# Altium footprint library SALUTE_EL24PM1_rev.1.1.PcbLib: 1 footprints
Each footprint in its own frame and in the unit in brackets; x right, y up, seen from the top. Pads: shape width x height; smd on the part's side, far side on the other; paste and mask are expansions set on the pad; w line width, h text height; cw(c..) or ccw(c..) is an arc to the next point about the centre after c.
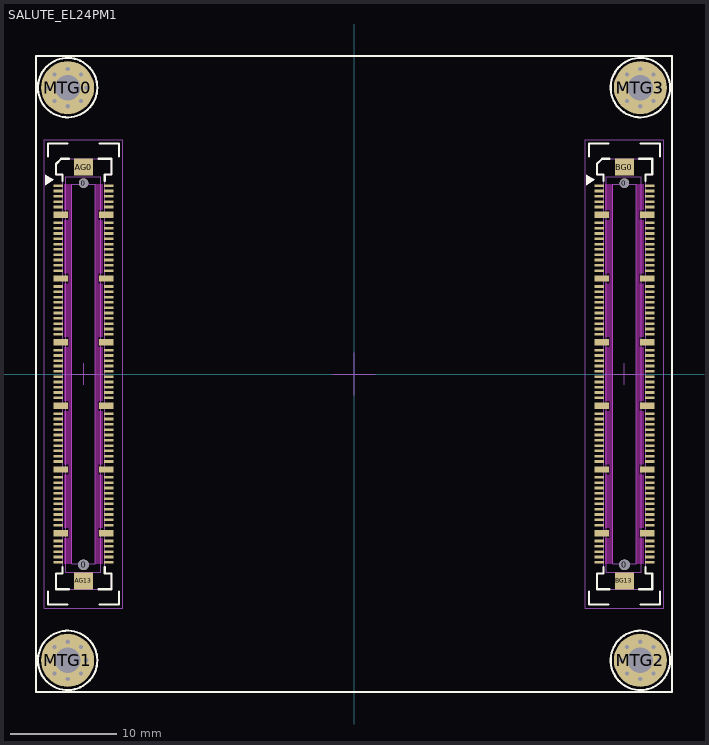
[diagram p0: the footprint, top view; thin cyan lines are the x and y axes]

## SALUTE_EL24PM1 [mm]
height 6
pads (276):
  round 1 hole 1 unplated mask+0.075: 0(-25.5,-18) 0(25.5,-18)
  round 0.9 hole 0.9 unplated mask+0.075: 0(-25.5,18) 0(25.5,18)
  rect 0.9x0.25 smd mask+0.075: A1(-27.875,17.75) A2(-23.125,17.75) A3(-27.875,17.25) A4(-23.125,17.25) A5(-27.875,16.75) A6(-23.125,16.75) A7(-27.875,16.25) A8(-23.125,16.25) A9(-27.875,15.75) A10(-23.125,15.75) A11(-27.875,14.25) A12(-23.125,14.25) A13(-27.875,13.75) A14(-23.125,13.75) A15(-27.875,13.25) A16(-23.125,13.25) A17(-27.875,12.75) A18(-23.125,12.75) A19(-27.875,12.25) A20(-23.125,12.25) A21(-27.875,11.75) A22(-23.125,11.75) A23(-27.875,11.25) A24(-23.125,11.25) A25(-27.875,10.75) A26(-23.125,10.75) A27(-27.875,10.25) A28(-23.125,10.25) A29(-27.875,9.75) A30(-23.125,9.75) A31(-27.875,8.25) A32(-23.125,8.25) A33(-27.875,7.75) A34(-23.125,7.75) A35(-27.875,7.25) A36(-23.125,7.25) A37(-27.875,6.75) A38(-23.125,6.75) A39(-27.875,6.25) A40(-23.125,6.25) A41(-27.875,5.75) A42(-23.125,5.75) A43(-27.875,5.25) A44(-23.125,5.25) A45(-27.875,4.75) A46(-23.125,4.75) A47(-27.875,4.25) A48(-23.125,4.25) A49(-27.875,3.75) A50(-23.125,3.75) A51(-27.875,2.25) A52(-23.125,2.25) A53(-27.875,1.75) A54(-23.125,1.75) A55(-27.875,1.25) A56(-23.125,1.25) A57(-27.875,0.75) A58(-23.125,0.75) A59(-27.875,0.25) A60(-23.125,0.25) A61(-27.875,-0.25) A62(-23.125,-0.25) A63(-27.875,-0.75) A64(-23.125,-0.75) A65(-27.875,-1.25) A66(-23.125,-1.25) A67(-27.875,-1.75) A68(-23.125,-1.75) A69(-27.875,-2.25) A70(-23.125,-2.25) A71(-27.875,-3.75) A72(-23.125,-3.75) A73(-27.875,-4.25) A74(-23.125,-4.25) A75(-27.875,-4.75) A76(-23.125,-4.75) A77(-27.875,-5.25) A78(-23.125,-5.25) A79(-27.875,-5.75) A80(-23.125,-5.75) A81(-27.875,-6.25) A82(-23.125,-6.25) A83(-27.875,-6.75) A84(-23.125,-6.75) A85(-27.875,-7.25) A86(-23.125,-7.25) A87(-27.875,-7.75) A88(-23.125,-7.75) A89(-27.875,-8.25) A90(-23.125,-8.25) A91(-27.875,-9.75) A92(-23.125,-9.75) A93(-27.875,-10.25) A94(-23.125,-10.25) A95(-27.875,-10.75) A96(-23.125,-10.75) A97(-27.875,-11.25) A98(-23.125,-11.25) A99(-27.875,-11.75) A100(-23.125,-11.75) A101(-27.875,-12.25) A102(-23.125,-12.25) A103(-27.875,-12.75) A104(-23.125,-12.75) A105(-27.875,-13.25) A106(-23.125,-13.25) A107(-27.875,-13.75) A108(-23.125,-13.75) A109(-27.875,-14.25) A110(-23.125,-14.25) A111(-27.875,-15.75) A112(-23.125,-15.75) A113(-27.875,-16.25) A114(-23.125,-16.25) A115(-27.875,-16.75) A116(-23.125,-16.75) A117(-27.875,-17.25) A118(-23.125,-17.25) A119(-27.875,-17.75) A120(-23.125,-17.75) B1(23.125,17.75) B2(27.875,17.75) B3(23.125,17.25) B4(27.875,17.25) B5(23.125,16.75) B6(27.875,16.75) B7(23.125,16.25) B8(27.875,16.25) B9(23.125,15.75) B10(27.875,15.75) B11(23.125,14.25) B12(27.875,14.25) B13(23.125,13.75) B14(27.875,13.75) B15(23.125,13.25) B16(27.875,13.25) B17(23.125,12.75) B18(27.875,12.75) B19(23.125,12.25) B20(27.875,12.25) B21(23.125,11.75) B22(27.875,11.75) B23(23.125,11.25) B24(27.875,11.25) B25(23.125,10.75) B26(27.875,10.75) B27(23.125,10.25) B28(27.875,10.25) B29(23.125,9.75) B30(27.875,9.75) B31(23.125,8.25) B32(27.875,8.25) B33(23.125,7.75) B34(27.875,7.75) B35(23.125,7.25) B36(27.875,7.25) B37(23.125,6.75) B38(27.875,6.75) B39(23.125,6.25) B40(27.875,6.25) B41(23.125,5.75) B42(27.875,5.75) B43(23.125,5.25) B44(27.875,5.25) B45(23.125,4.75) B46(27.875,4.75) B47(23.125,4.25) B48(27.875,4.25) B49(23.125,3.75) B50(27.875,3.75) B51(23.125,2.25) B52(27.875,2.25) B53(23.125,1.75) B54(27.875,1.75) B55(23.125,1.25) B56(27.875,1.25) B57(23.125,0.75) B58(27.875,0.75) B59(23.125,0.25) B60(27.875,0.25) B61(23.125,-0.25) B62(27.875,-0.25) B63(23.125,-0.75) B64(27.875,-0.75) B65(23.125,-1.25) B66(27.875,-1.25) B67(23.125,-1.75) B68(27.875,-1.75) B69(23.125,-2.25) B70(27.875,-2.25) B71(23.125,-3.75) B72(27.875,-3.75) B73(23.125,-4.25) B74(27.875,-4.25) B75(23.125,-4.75) B76(27.875,-4.75) B77(23.125,-5.25) B78(27.875,-5.25) B79(23.125,-5.75) B80(27.875,-5.75) B81(23.125,-6.25) B82(27.875,-6.25) B83(23.125,-6.75) B84(27.875,-6.75) B85(23.125,-7.25) B86(27.875,-7.25) B87(23.125,-7.75) B88(27.875,-7.75) B89(23.125,-8.25) B90(27.875,-8.25) B91(23.125,-9.75) B92(27.875,-9.75) B93(23.125,-10.25) B94(27.875,-10.25) B95(23.125,-10.75) B96(27.875,-10.75) B97(23.125,-11.25) B98(27.875,-11.25) B99(23.125,-11.75) B100(27.875,-11.75) B101(23.125,-12.25) B102(27.875,-12.25) B103(23.125,-12.75) B104(27.875,-12.75) B105(23.125,-13.25) B106(27.875,-13.25) B107(23.125,-13.75) B108(27.875,-13.75) B109(23.125,-14.25) B110(27.875,-14.25) B111(23.125,-15.75) B112(27.875,-15.75) B113(23.125,-16.25) B114(27.875,-16.25) B115(23.125,-16.75) B116(27.875,-16.75) B117(23.125,-17.25) B118(27.875,-17.25) B119(23.125,-17.75) B120(27.875,-17.75)
  rect 1.8x1.6 smd mask+0.075: AG0(-25.5,19.5) AG13(-25.5,-19.5) BG0(25.5,19.5) BG13(25.5,-19.5)
  rect 1.35x0.6 smd mask+0.075: AG1(-27.65,15) AG2(-23.35,15) AG3(-27.65,9) AG4(-23.35,9) AG5(-27.65,3) AG6(-23.35,3) AG7(-27.65,-3) AG8(-23.35,-3) AG9(-27.65,-9) AG10(-23.35,-9) AG11(-27.65,-15) AG12(-23.35,-15) BG1(23.35,15) BG2(27.65,15) BG3(23.35,9) BG4(27.65,9) BG5(23.35,3) BG6(27.65,3) BG7(23.35,-3) BG8(27.65,-3) BG9(23.35,-9) BG10(27.65,-9) BG11(23.35,-15) BG12(27.65,-15)
  round 5 / inner round 3.6 / far side round 5 hole 2.4: MTG0(-27,27) MTG1(-27,-27) MTG2(27,-27) MTG3(27,27)
via 25.75,28.25 diameter 1 hole 0.4
via 27,28.75 diameter 1 hole 0.4
via 28.25,28.25 diameter 1 hole 0.4
via 28.75,27 diameter 1 hole 0.4
via 28.25,25.75 diameter 1 hole 0.4
via 27,25.25 diameter 1 hole 0.4
via 25.75,25.75 diameter 1 hole 0.4
via 25.2,27 diameter 1 hole 0.4
via 25.75,-25.75 diameter 1 hole 0.4
via 27,-25.25 diameter 1 hole 0.4
via 28.25,-25.75 diameter 1 hole 0.4
via 28.75,-27 diameter 1 hole 0.4
via 28.25,-28.25 diameter 1 hole 0.4
via 27,-28.75 diameter 1 hole 0.4
via 25.75,-28.25 diameter 1 hole 0.4
via 25.2,-27 diameter 1 hole 0.4
via -28.25,-25.75 diameter 1 hole 0.4
via -27,-25.25 diameter 1 hole 0.4
via -25.75,-25.75 diameter 1 hole 0.4
via -25.25,-27 diameter 1 hole 0.4
via -25.75,-28.25 diameter 1 hole 0.4
via -27,-28.75 diameter 1 hole 0.4
via -28.25,-28.25 diameter 1 hole 0.4
via -28.8,-27 diameter 1 hole 0.4
via -28.8,27 diameter 1 hole 0.4
via -28.25,25.75 diameter 1 hole 0.4
via -27,25.25 diameter 1 hole 0.4
via -25.75,25.75 diameter 1 hole 0.4
via -25.25,27 diameter 1 hole 0.4
via -25.75,28.25 diameter 1 hole 0.4
via -27,28.75 diameter 1 hole 0.4
via -28.25,28.25 diameter 1 hole 0.4
Top Layer keep-out:
  region: 23.7,14.5 24.1,14.5 24.1,15.5 23.7,15.5 23.7,17.9 24.4,17.9 24.4,-17.9 23.7,-17.9 23.7,-15.5 24.1,-15.5 24.1,-14.5 23.7,-14.5 23.7,-9.5 24.1,-9.5 24.1,-8.5 23.7,-8.5 23.7,-3.5 24.1,-3.5 24.1,-2.5 23.7,-2.5 23.7,2.5 24.1,2.5 24.1,3.5 23.7,3.5 23.7,8.5 24.1,8.5 24.1,9.5 23.7,9.5
  region: 27.3,14.5 26.9,14.5 26.9,15.5 27.3,15.5 27.3,17.9 26.6,17.9 26.6,-17.9 27.3,-17.9 27.3,-15.5 26.9,-15.5 26.9,-14.5 27.3,-14.5 27.3,-9.5 26.9,-9.5 26.9,-8.5 27.3,-8.5 27.3,-3.5 26.9,-3.5 26.9,-2.5 27.3,-2.5 27.3,2.5 26.9,2.5 26.9,3.5 27.3,3.5 27.3,8.5 26.9,8.5 26.9,9.5 27.3,9.5
  region: -23.7,14.5 -24.1,14.5 -24.1,15.5 -23.7,15.5 -23.7,17.9 -24.4,17.9 -24.4,-17.9 -23.7,-17.9 -23.7,-15.5 -24.1,-15.5 -24.1,-14.5 -23.7,-14.5 -23.7,-9.5 -24.1,-9.5 -24.1,-8.5 -23.7,-8.5 -23.7,-3.5 -24.1,-3.5 -24.1,-2.5 -23.7,-2.5 -23.7,2.5 -24.1,2.5 -24.1,3.5 -23.7,3.5 -23.7,8.5 -24.1,8.5 -24.1,9.5 -23.7,9.5
  region: -27.3,14.5 -26.9,14.5 -26.9,15.5 -27.3,15.5 -27.3,17.9 -26.6,17.9 -26.6,-17.9 -27.3,-17.9 -27.3,-15.5 -26.9,-15.5 -26.9,-14.5 -27.3,-14.5 -27.3,-9.5 -26.9,-9.5 -26.9,-8.5 -27.3,-8.5 -27.3,-3.5 -26.9,-3.5 -26.9,-2.5 -27.3,-2.5 -27.3,2.5 -26.9,2.5 -26.9,3.5 -27.3,3.5 -27.3,8.5 -26.9,8.5 -26.9,9.5 -27.3,9.5
Top Overlay:
  circle w0.2: c27,27 r2.8
  circle w0.2: c27,-27 r2.8
  circle w0.2: c-27,-27 r2.8
  circle w0.2: c-27,27 r2.8
  region: 21.9,17.8 21.9,18.8 22.7,18.3
  region: -29.1,17.8 -29.1,18.8 -28.3,18.3
  lines w0.1: -22.875,-20.3 -22.875,-20.3 ; -22.875,20.3 -22.875,20.3 ; 28.125,-20.3 28.125,-20.3 ; 28.125,20.3 28.125,20.3
  lines w0.2: -28.85,-20.5 -28.85,-21.75 -27,-21.75 ; -28.85,20.5 -28.85,21.75 -27,21.75 ; -27.475,-18.2 -27.475,-18.8 -28.1,-18.8 -28.1,-20.3 -26.9,-20.3 ; -27.475,18.2 -27.475,18.8 -28.1,18.8 -28.1,19.8 -27.6,20.3 -26.9,20.3 ; -24.1,-20.3 -22.875,-20.3 -22.875,-18.8 -23.5,-18.8 -23.5,-18.2 ; -24.1,20.3 -22.875,20.3 -22.875,18.8 -23.5,18.8 -23.5,18.2 ; -24,-21.75 -22.15,-21.75 -22.15,-20.5 ; -24,21.75 -22.15,21.75 -22.15,20.5 ; 22.15,-20.5 22.15,-21.75 24,-21.75 ; 22.15,20.5 22.15,21.75 24,21.75 ; 23.525,-18.2 23.525,-18.8 22.9,-18.8 22.9,-20.3 24.1,-20.3 ; 23.525,18.2 23.525,18.8 22.9,18.8 22.9,19.8 23.4,20.3 24.1,20.3 ; 26.9,-20.3 28.125,-20.3 28.125,-18.8 27.5,-18.8 27.5,-18.2 ; 26.9,20.3 28.125,20.3 28.125,18.8 27.5,18.8 27.5,18.2 ; 27,-21.75 28.85,-21.75 28.85,-20.5 ; 27,21.75 28.85,21.75 28.85,20.5 ; -30,-30 30,-30 30,30 -30,30 -30,-30
Mechanical 13:
  region: 21.9,17.8 21.9,18.8 22.7,18.3
  region: -29.1,17.8 -29.1,18.8 -28.3,18.3
  lines w0.1: -2,0 2,0 ; 0,-2 0,2 ; -28.125,-20.3 -22.875,-20.3 -22.875,-18.8 -23.5,-18.8 -23.5,18.8 -22.875,18.8 -22.875,20.275 -27.625,20.275 -28.1,19.8 -28.1,18.8 -27.5,18.8 -27.475,18.775 -27.475,-18.8 -28.1,-18.8 -28.125,-18.825 -28.125,-20.3 ; -27.2,-18.7 -27.2,18.6 -23.9,18.6 -23.9,-18.7 -27.2,-18.7 ; -26.625,-17.875 -26.625,17.875 -24.375,17.875 -24.375,-17.875 -26.625,-17.875 ; -22.875,20.3 ccw(c-22.875,20.3) -22.875,20.3 ; 22.875,-20.3 22.875,-18.825 22.9,-18.8 23.525,-18.8 23.525,18.775 23.5,18.8 22.9,18.8 22.9,19.8 23.375,20.275 28.125,20.275 28.125,18.8 27.5,18.8 27.5,-18.8 28.125,-18.8 28.125,-20.3 22.875,-20.3 ; 23.8,-18.7 27.1,-18.7 27.1,18.6 23.8,18.6 23.8,-18.7 ; 24.375,-17.875 26.625,-17.875 26.625,17.875 24.375,17.875 24.375,-17.875 ; 28.125,20.3 ccw(c28.125,20.3) 28.125,20.3
  lines w0.2: -29,27 -25,27 ; -27,25 -27,29 ; -30,-30 -30,30 30,30 30,-30 -30,-30 ; -29,-27 -25,-27 -29,-27 ; -27,-29 -27,-25 -27,-29 ; 25,-27 29,-27 25,-27 ; 25,27 29,27 25,27 ; 27,-29 27,-25 27,-29 ; 27,25 27,29 27,25
Mechanical 15:
  circle w0.05: c27,27 r2.8
  circle w0.05: c27,-27 r2.8
  circle w0.05: c-27,-27 r2.8
  circle w0.05: c-27,27 r2.8
  lines w0.05: -29.2,-22.1 -29.2,22.1 -21.8,22.1 -21.8,-22.1 -29.2,-22.1 ; 21.8,-22.1 29.2,-22.1 29.2,22.1 21.8,22.1 21.8,-22.1
  lines w0.1: -26.5,0 -24.5,0 ; -25.5,-1 -25.5,1 ; 24.5,0 26.5,0 ; 25.5,-1 25.5,1
3D body: height 1.61, standoff -0.62, extent 22.875,-20.3 28.125,20.3
3D body: height 1.61, standoff -0.62, extent -28.125,-20.3 -22.875,20.3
